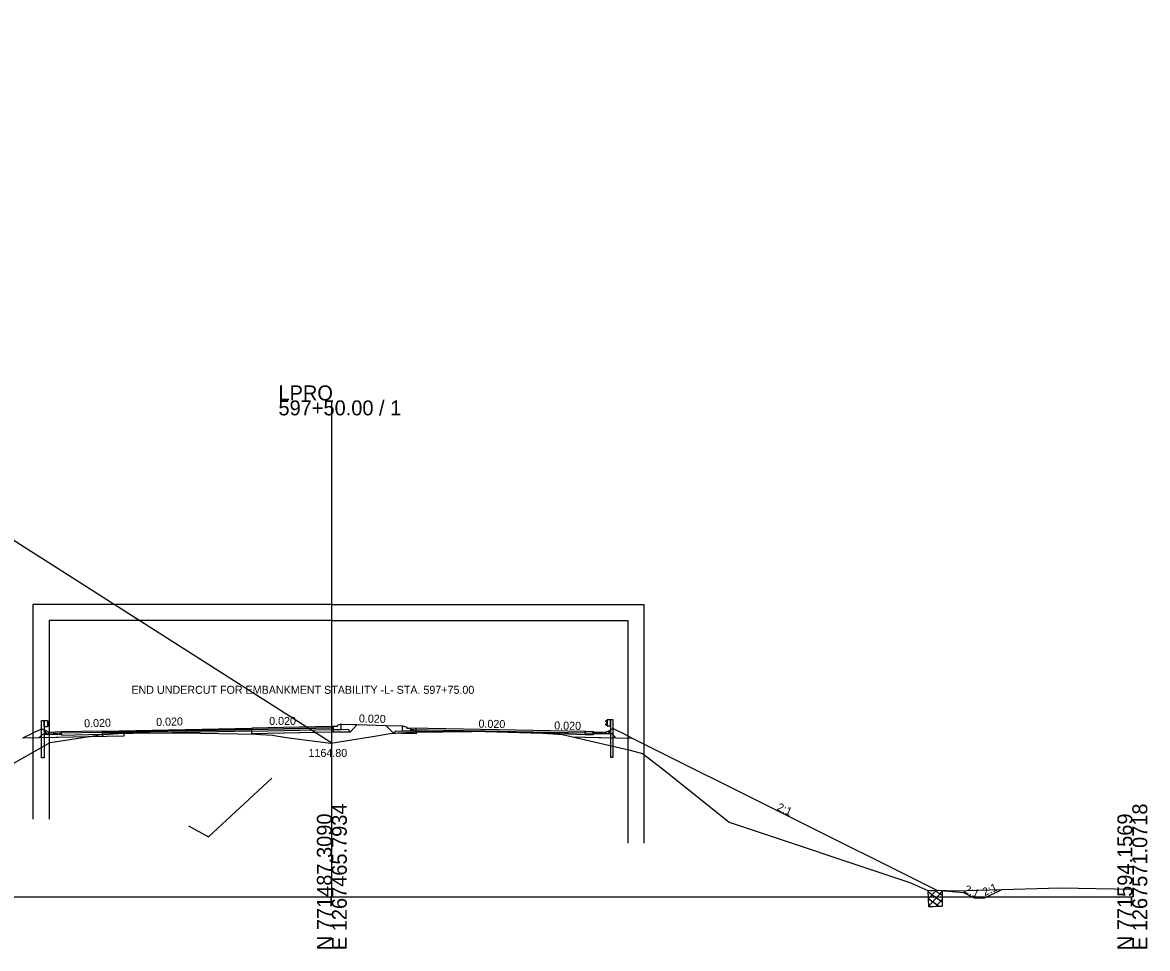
# Model space of a CAD drawing. Extents: x -3833 to 1267678, y -522 to 773248.
# Drawn here: x 92 to 302.8, y 8490.3 to 8663.9 of the extents above; entities that cross this region are included whole.
import ezdxf

# ---------------------------------------------------------------- set-up
doc = ezdxf.new("R2010")
doc.units = 0
for name, color, linetype in [('Exist Cross Section Cell', 7, 'Continuous'), ('Exist XS Center Line Elevation Label', 7, 'Continuous'), ('Exist XS Ground Line', 7, 'Continuous'), ('Prop CMT DNC', 7, 'Continuous'), ('Prop CMT Guardrail Graphics', 7, 'Continuous'), ('Prop CMT Pvmt Course 1', 7, 'Continuous'), ('Prop CMT Pvmt Course 2', 7, 'Continuous'), ('Prop CMT Pvmt Course 4', 7, 'Continuous'), ('Prop CMT Shld Paved Course 1', 7, 'Continuous'), ('Prop CMT Shld Paved Course 2', 7, 'Continuous'), ('Prop CMT Shld Paved Course 4', 7, 'Continuous'), ('Prop CMT Slope Grass', 7, 'Continuous'), ('Prop CMT Subgrade Earthwork', 7, 'Continuous'), ('Prop Conc Curb and Gutter', 7, 'Continuous'), ('Prop Conc Island Cover', 7, 'Continuous'), ('Prop Corridor Mesh Bottom', 7, 'Continuous'), ('Prop XS Ditch Slope Text', 7, 'Continuous'), ('Prop XS Finish Grade', 7, 'Continuous'), ('Prop XS Label Text', 7, 'Continuous'), ('Prop XS SE Text', 7, 'Continuous'), ('Prop XS Undercut Exc', 7, 'Continuous'), ('Scratch_Level_1', 7, 'Continuous'), ('Scratch_Level_3', 7, 'Continuous'), ('Scratch_Level_5', 7, 'Continuous'), ('Typical Curb CELL', 7, 'Continuous')]:
    doc.layers.add(name, color=color, linetype=linetype)

msp = doc.modelspace()

# ---------------------------------------------------------------- linework, layer by layer
at = {"layer": 'Exist Cross Section Cell'}
for p, q in [((150, 8500), (150, 8593.03)), ((0, 8500), (150, 8500)), ((150, 8500), (300, 8500))]:
    msp.add_line(p, q, dxfattribs=at)
at = {"layer": 'Exist XS Ground Line'}
for p, q in [((97.19, 8528.92), (105.76, 8530.24)), ((105.76, 8530.24), (106.67, 8530.39)), ((106.67, 8530.39), (107.2, 8530.42)), ((107.2, 8530.42), (110.96, 8530.64)), ((110.96, 8530.64), (112.73, 8530.65)), ((112.73, 8530.65), (122.54, 8530.7)), ((122.54, 8530.7), (125.34, 8530.65)), ((125.34, 8530.65), (135.95, 8530.46)), ((135.95, 8530.46), (136.62, 8530.42)), ((136.62, 8530.42), (138.94, 8530.31)), ((138.94, 8530.31), (139.56, 8530.17)), ((139.56, 8530.17), (141.91, 8529.8)), ((141.91, 8529.8), (148.29, 8528.98)), ((150.97, 8528.97), (157.63, 8530.03)), ((157.63, 8530.03), (160.94, 8530.63)), ((160.94, 8530.63), (162.02, 8530.68)), ((162.02, 8530.68), (162.38, 8530.7)), ((162.38, 8530.7), (165.35, 8530.83)), ((165.35, 8530.83), (176.22, 8531)), ((176.22, 8531), (176.62, 8531.01)), ((176.62, 8531.01), (178.72, 8530.95)), ((178.72, 8530.95), (189.53, 8530.67)), ((189.53, 8530.67), (193.23, 8530.4)), ((193.23, 8530.4), (200.22, 8528.78)), ((90.31, 8525), (97.19, 8528.92)), ((148.29, 8528.98), (149.81, 8528.76)), ((149.81, 8528.76), (150.97, 8528.97)), ((200.22, 8528.78), (205.63, 8527.53)), ((205.63, 8527.53), (208.23, 8526.86)), ((208.23, 8526.86), (212.2, 8523.77)), ((212.2, 8523.77), (224.47, 8513.99)), ((224.47, 8513.99), (258.31, 8502.67)), ((258.31, 8502.67), (261.7, 8501.2)), ((261.7, 8501.2), (262.71, 8501.17)), ((262.71, 8501.17), (263.74, 8501.24)), ((263.74, 8501.24), (266.72, 8501.14)), ((266.72, 8501.14), (286.47, 8501.67)), ((286.47, 8501.67), (300, 8501.43))]:
    msp.add_line(p, q, dxfattribs=at)
at = {"layer": 'Prop CMT Guardrail Graphics'}
for p, q in [((95.59, 8530.54), (95.59, 8533.04)), ((95.59, 8533.04), (96.07, 8533.04)), ((96.07, 8533.04), (96.07, 8530.53)), ((96.07, 8531.86), (96.07, 8533.04)), ((96.07, 8533.04), (96.74, 8533.04)), ((96.74, 8531.86), (96.07, 8531.86)), ((96.74, 8533.04), (96.74, 8531.86)), ((96.74, 8532.96), (96.74, 8531.93)), ((96.84, 8532.94), (96.74, 8532.96)), ((96.74, 8531.93), (96.84, 8531.96)), ((96.75, 8532.49), (96.98, 8532.69)), ((96.75, 8532.4), (96.75, 8532.49)), ((96.98, 8532.2), (96.75, 8532.4)), ((96.98, 8532.84), (96.84, 8532.94)), ((96.84, 8531.96), (96.98, 8532.06)), ((96.98, 8532.69), (96.98, 8532.84)), ((96.98, 8532.06), (96.98, 8532.2)), ((201.32, 8532.99), (201.46, 8533.09)), ((201.32, 8532.85), (201.32, 8532.99)), ((201.54, 8532.65), (201.32, 8532.85)), ((201.32, 8532.36), (201.54, 8532.56)), ((201.32, 8532.21), (201.32, 8532.36)), ((201.46, 8532.11), (201.32, 8532.21)), ((201.46, 8533.09), (201.56, 8533.11)), ((201.56, 8532.09), (201.46, 8532.11)), ((201.54, 8532.56), (201.54, 8532.65)), ((201.56, 8533.19), (201.56, 8532.01)), ((202.23, 8533.19), (201.56, 8533.19)), ((201.56, 8533.11), (201.56, 8532.09)), ((201.56, 8532.01), (202.23, 8532.01)), ((202.71, 8533.19), (202.23, 8533.19)), ((202.23, 8532.01), (202.23, 8533.19)), ((202.23, 8533.19), (202.23, 8530.68)), ((202.71, 8530.69), (202.71, 8533.19)), ((95.59, 8526.03), (95.59, 8530.54)), ((96.07, 8530.53), (96.07, 8526.03)), ((202.23, 8530.68), (202.23, 8526.18)), ((202.71, 8526.18), (202.71, 8530.69)), ((96.07, 8526.03), (95.59, 8526.03)), ((202.23, 8526.18), (202.71, 8526.18))]:
    msp.add_line(p, q, dxfattribs=at)
at = {"layer": 'Prop CMT Pvmt Course 1'}
for p, q in [((107, 8531.05), (135, 8531.61)), ((135, 8531.36), (107, 8530.8)), ((135, 8531.61), (135, 8531.61)), ((135, 8531.61), (135, 8531.61)), ((135, 8531.61), (135, 8531.36)), ((135, 8531.36), (135, 8531.36)), ((197.48, 8530.96), (164.78, 8531.61)), ((164.78, 8531.61), (164.78, 8531.61)), ((164.78, 8531.61), (164.78, 8531.61)), ((164.78, 8531.61), (164.78, 8531.36)), ((164.78, 8531.36), (197.48, 8530.71)), ((164.78, 8531.36), (165, 8531.36)), ((107, 8530.8), (107, 8531.05)), ((107, 8531.05), (107, 8531.05)), ((197.48, 8530.71), (197.48, 8530.96)), ((197.48, 8530.96), (197.48, 8530.96))]:
    msp.add_line(p, q, dxfattribs=at)
at = {"layer": 'Prop CMT Pvmt Course 2'}
for p, q in [((150, 8531.66), (135, 8531.36)), ((135, 8531.36), (135, 8531.36)), ((135, 8531.36), (135, 8531.03)), ((150.24, 8531.65), (150, 8531.66)), ((150, 8531.66), (150, 8531.66)), ((150, 8531.66), (150, 8531.66)), ((150.25, 8531.32), (150.24, 8531.65)), ((150.24, 8531.65), (150.24, 8531.65)), ((135, 8531.02), (150, 8531.33)), ((135, 8531.03), (135, 8531.02)), ((150, 8531.33), (150, 8531.33)), ((150, 8531.33), (150, 8531.33)), ((150, 8531.33), (150.25, 8531.32)), ((150.25, 8531.32), (150.25, 8531.32))]:
    msp.add_line(p, q, dxfattribs=at)
at = {"layer": 'Prop CMT Pvmt Course 4'}
for p, q in [((153.04, 8531.37), (150.25, 8531.32)), ((153.49, 8530.92), (153.04, 8531.37)), ((165.78, 8531.36), (165.78, 8531.59)), ((165.78, 8530.55), (165.78, 8531.36)), ((135, 8531.02), (150, 8531.33)), ((135, 8530.57), (135, 8531.03)), ((135, 8531.03), (135, 8531.03)), ((135, 8531.03), (135, 8531.02)), ((150, 8530.87), (135, 8530.57)), ((150, 8531.33), (150, 8531.33)), ((150, 8531.33), (150, 8531.33)), ((150, 8531.33), (150.25, 8531.32)), ((150.24, 8530.86), (150, 8530.87)), ((150, 8530.87), (150, 8530.87)), ((150, 8530.87), (150, 8530.87)), ((150.24, 8531.32), (150.24, 8530.86)), ((150.25, 8531.32), (150.24, 8531.32)), ((150.25, 8531.32), (150.24, 8530.86)), ((150.24, 8530.86), (153.49, 8530.92)), ((150.24, 8530.86), (150.24, 8530.86)), ((150.24, 8530.86), (150.24, 8530.86)), ((150.25, 8531.32), (150.25, 8531.32)), ((150.25, 8531.32), (150.25, 8531.32)), ((161.53, 8530.64), (161.98, 8531.08)), ((164.78, 8530.57), (161.53, 8530.64)), ((161.98, 8531.08), (164.78, 8531.03))]:
    msp.add_line(p, q, dxfattribs=at)
at = {"layer": 'Prop CMT Shld Paved Course 1'}
for p, q in [((150, 8531.91), (135, 8531.61)), ((135, 8531.36), (150, 8531.66)), ((135, 8531.61), (135, 8531.61)), ((135, 8531.61), (135, 8531.36)), ((150.24, 8531.9), (150, 8531.91)), ((150, 8531.91), (150, 8531.91)), ((150, 8531.91), (150, 8531.91)), ((150, 8531.66), (150, 8531.66)), ((150, 8531.66), (150, 8531.66)), ((150, 8531.66), (150.24, 8531.65)), ((150.24, 8531.65), (150.24, 8531.9)), ((150.24, 8531.9), (150.24, 8531.9)), ((164.78, 8531.36), (164.78, 8531.61)), ((96.99, 8530.52), (96.99, 8530.52)), ((96.99, 8530.52), (96.99, 8530.52)), ((97.01, 8530.81), (97.01, 8530.81)), ((97.01, 8530.81), (97.01, 8530.81)), ((97.01, 8530.81), (97.01, 8530.81)), ((97.01, 8530.81), (97.01, 8530.81)), ((97.01, 8530.81), (97.01, 8530.81)), ((97.19, 8530.51), (97.19, 8530.51)), ((97.19, 8530.51), (97.19, 8530.51)), ((97.19, 8530.51), (97.19, 8530.51)), ((97.19, 8530.51), (97.19, 8530.51)), ((97.19, 8530.51), (97.19, 8530.51)), ((97.19, 8530.51), (97.19, 8530.51)), ((107, 8531.05), (99.33, 8530.89)), ((107, 8530.8), (107, 8531.05)), ((107, 8531.05), (107, 8531.05)), ((107, 8531.05), (107, 8531.05)), ((107, 8530.8), (107, 8530.8)), ((197.48, 8530.96), (197.48, 8530.71)), ((198.99, 8530.93), (197.48, 8530.96)), ((197.48, 8530.71), (198.99, 8530.68))]:
    msp.add_line(p, q, dxfattribs=at)
at = {"layer": 'Prop CMT Shld Paved Course 2'}
for p, q in [((125.34, 8531.16), (135, 8531.36)), ((135, 8531.36), (135, 8531.36)), ((135, 8531.36), (135, 8531.36)), ((135, 8531.36), (135, 8531.02)), ((164.78, 8531.03), (164.78, 8531.36)), ((164.78, 8531.36), (164.78, 8531.36)), ((164.78, 8531.36), (165.35, 8531.35)), ((165.35, 8531.35), (165.35, 8531.35)), ((165.35, 8531.35), (165.35, 8531.35)), ((165.35, 8531.35), (176.22, 8531.13)), ((96.65, 8530.18), (96.65, 8530.18)), ((96.76, 8530.56), (96.76, 8530.56)), ((96.85, 8530.17), (96.85, 8530.17)), ((96.85, 8530.17), (96.85, 8530.17)), ((96.85, 8530.17), (96.85, 8530.17)), ((96.85, 8530.17), (96.85, 8530.17)), ((96.99, 8530.52), (96.99, 8530.52)), ((97.19, 8530.51), (97.19, 8530.51)), ((97.19, 8530.51), (97.19, 8530.51)), ((107, 8530.8), (99.33, 8530.64)), ((107, 8530.8), (112.73, 8530.91)), ((107, 8530.46), (107, 8530.8)), ((107, 8530.8), (107, 8530.8)), ((107, 8530.8), (107, 8530.8)), ((107, 8530.46), (107, 8530.8)), ((107, 8530.8), (107, 8530.8)), ((110.96, 8530.64), (107, 8530.46)), ((107, 8530.46), (107, 8530.46)), ((112.73, 8530.65), (110.96, 8530.64)), ((112.73, 8530.91), (122.54, 8531.11)), ((112.73, 8530.91), (112.73, 8530.91)), ((117.65, 8530.68), (112.73, 8530.65)), ((112.73, 8530.65), (112.73, 8530.65)), ((122.54, 8530.77), (117.65, 8530.68)), ((117.65, 8530.68), (117.65, 8530.68)), ((122.54, 8531.11), (125.34, 8531.16)), ((122.54, 8531.11), (122.54, 8531.11)), ((125.34, 8530.83), (122.54, 8530.77)), ((122.54, 8530.77), (122.54, 8530.77)), ((125.34, 8531.16), (125.34, 8531.16)), ((135, 8531.02), (125.34, 8530.83)), ((125.34, 8530.83), (125.34, 8530.83)), ((135, 8531.02), (135, 8531.02)), ((165.35, 8531.02), (164.78, 8531.03)), ((170.54, 8530.91), (165.35, 8531.02)), ((165.35, 8531.02), (165.35, 8531.02)), ((165.35, 8531.02), (165.35, 8531.02)), ((176.22, 8531), (170.54, 8530.91)), ((170.54, 8530.91), (170.54, 8530.91)), ((176.22, 8531.13), (176.22, 8531.13)), ((176.22, 8531.13), (176.62, 8531.12)), ((176.62, 8531.01), (176.22, 8531)), ((176.22, 8531), (176.22, 8531)), ((176.62, 8531.12), (178.72, 8531.08)), ((178.72, 8530.95), (176.62, 8531.01)), ((178.72, 8531.08), (178.72, 8531.08)), ((178.72, 8531.08), (189.53, 8530.87)), ((189.53, 8530.67), (178.72, 8530.95)), ((178.72, 8530.95), (178.72, 8530.95)), ((189.53, 8530.87), (189.53, 8530.87)), ((189.53, 8530.87), (189.8, 8530.86)), ((189.8, 8530.65), (189.53, 8530.67)), ((189.53, 8530.67), (189.53, 8530.67)), ((189.8, 8530.86), (197.48, 8530.71)), ((197.48, 8530.38), (189.8, 8530.65)), ((197.48, 8530.71), (197.48, 8530.71)), ((197.48, 8530.71), (197.48, 8530.38)), ((197.48, 8530.71), (197.48, 8530.38))]:
    msp.add_line(p, q, dxfattribs=at)
at = {"layer": 'Prop CMT Shld Paved Course 4'}
for p, q in [((95.1, 8529.76), (95.82, 8530.48)), ((95.82, 8530.48), (96.32, 8530.48)), ((107, 8530.01), (95.94, 8529.78)), ((99.34, 8530.48), (99.34, 8530.31)), ((99.34, 8530.31), (107, 8530.46)), ((107, 8530.46), (107, 8530.01)), ((197.48, 8530.38), (189.8, 8530.65)), ((189.8, 8530.65), (193.23, 8530.4)), ((193.23, 8530.4), (195.12, 8529.97)), ((195.12, 8529.97), (202.39, 8529.82)), ((198.99, 8530.35), (197.48, 8530.38)), ((198.99, 8530.51), (198.99, 8530.35)), ((202.52, 8530.51), (202.01, 8530.51)), ((203.23, 8529.8), (202.52, 8530.51))]:
    msp.add_line(p, q, dxfattribs=at)
at = {"layer": 'Prop CMT Slope Grass'}
for p, q in [((95.63, 8531.5), (93.71, 8530.55)), ((95.63, 8531.5), (96.32, 8531.15)), ((151.87, 8532.33), (154.77, 8532.26)), ((160.1, 8532.12), (163.27, 8532.04)), ((202.71, 8531.54), (202.01, 8531.19)), ((202.71, 8531.54), (204.62, 8530.58)), ((93.71, 8530.55), (92.03, 8529.71)), ((204.62, 8530.58), (206.3, 8529.74))]:
    msp.add_line(p, q, dxfattribs=at)
at = {"layer": 'Prop CMT Subgrade Earthwork'}
for p, q in [((153.49, 8530.92), (154.77, 8532.26)), ((161.53, 8530.64), (160.1, 8532.12)), ((111, 8530.09), (92.03, 8529.71)), ((111, 8530.64), (111, 8530.09)), ((150.24, 8530.86), (135, 8530.57)), ((135, 8530.57), (135, 8530.48)), ((153.49, 8530.92), (150.24, 8530.86)), ((165.78, 8530.55), (161.53, 8530.64)), ((165.78, 8530.84), (165.78, 8530.55)), ((195.12, 8529.97), (197.47, 8529.92)), ((197.47, 8529.92), (206.3, 8529.74))]:
    msp.add_line(p, q, dxfattribs=at)
at = {"layer": 'Prop Conc Curb and Gutter'}
for p, q in [((150.24, 8531.9), (150.24, 8531.9)), ((150.24, 8531.9), (150.24, 8531.32)), ((150.25, 8531.9), (150.24, 8531.9)), ((150.99, 8531.92), (150.25, 8531.9)), ((150.25, 8531.32), (151.75, 8531.35)), ((151, 8531.92), (150.99, 8531.92)), ((151.75, 8532.33), (151, 8532.08)), ((151, 8532.08), (151, 8532.08)), ((151, 8532.08), (151, 8531.92)), ((151.76, 8532.33), (151.75, 8532.33)), ((151.75, 8531.35), (151.76, 8531.35)), ((151.76, 8531.35), (151.76, 8532.33)), ((151.76, 8532.33), (151.76, 8532.33)), ((163.27, 8532.03), (163.27, 8532.04)), ((163.27, 8532.04), (163.28, 8532.04)), ((163.27, 8531.06), (163.27, 8532.03)), ((163.28, 8532.04), (164.03, 8531.79)), ((164.03, 8531.79), (164.03, 8531.79)), ((164.03, 8531.79), (164.03, 8531.63)), ((164.03, 8531.63), (164.04, 8531.63)), ((164.04, 8531.63), (164.78, 8531.61)), ((164.78, 8531.61), (164.78, 8531.61)), ((164.78, 8531.61), (164.78, 8531.03)), ((150.24, 8531.32), (150.25, 8531.32)), ((163.29, 8531.06), (163.27, 8531.06)), ((164.78, 8531.03), (163.29, 8531.06))]:
    msp.add_line(p, q, dxfattribs=at)
at = {"layer": 'Prop Conc Island Cover'}
for p, q in [((151.76, 8532.08), (151.76, 8532.33)), ((151.76, 8532.33), (151.87, 8532.33)), ((163.27, 8532.04), (163.27, 8531.79))]:
    msp.add_line(p, q, dxfattribs=at)
at = {"layer": 'Prop Corridor Mesh Bottom'}
for p, q in [((135, 8531.61), (135, 8531.36)), ((111, 8531.13), (111, 8530.88))]:
    msp.add_line(p, q, dxfattribs=at)
at = {"layer": 'Prop XS Finish Grade'}
for p, q in [((151.76, 8532.33), (151.87, 8532.33)), ((153.91, 8532.28), (154.19, 8532.27)), ((154.77, 8532.26), (160.1, 8532.12)), ((206.3, 8529.74), (263.36, 8501.21))]:
    msp.add_line(p, q, dxfattribs=at)
msp.add_lwpolyline([(263.36, 8501.21), (268.36, 8500.8), (270.36, 8499.8), (272.36, 8499.8), (275.54, 8501.39)], dxfattribs=at)
at = {"layer": 'Prop XS Undercut Exc'}
for p, q in [((261.7, 8501.2), (261.78, 8498.19)), ((261.84, 8501.19), (261.7, 8501.05)), ((261.71, 8500.91), (264.36, 8499.08)), ((263.21, 8501.2), (261.74, 8499.62)), ((264.36, 8500.97), (261.79, 8498.19)), ((263.06, 8501.19), (264.36, 8500.3)), ((264.36, 8501.22), (264.36, 8498.22)), ((261.74, 8499.67), (263.82, 8498.24)), ((261.77, 8498.44), (262.14, 8498.18)), ((261.78, 8498.19), (262.77, 8498.16)), ((262.77, 8498.16), (263.8, 8498.24)), ((264.36, 8499.5), (263.15, 8498.19)), ((263.8, 8498.24), (264.36, 8498.22))]:
    msp.add_line(p, q, dxfattribs=at)
at = {"layer": 'Scratch_Level_1'}
msp.add_line((150, 8528.8), (-62.25, 8663.86), dxfattribs=at)
at = {"layer": 'Scratch_Level_3'}
msp.add_lwpolyline([(111, 8530.64), (111, 8530.09)], dxfattribs=at)
at = {"layer": 'Scratch_Level_5'}
for p, q in [((126.9, 8511.21), (138.76, 8522.24)), ((123.11, 8513.32), (126.9, 8511.21))]:
    msp.add_line(p, q, dxfattribs=at)
for points in [[(150, 8554.8), (94, 8554.8), (94, 8514.54)], [(150, 8554.8), (208.45, 8554.8), (208.45, 8510.08)], [(150, 8551.8), (97, 8551.8), (97, 8514.54)], [(150, 8551.8), (205.45, 8551.8), (205.45, 8510.08)]]:
    msp.add_lwpolyline(points, dxfattribs=at)
at = {"layer": 'Typical Curb CELL'}
for p, q in [((96.32, 8530.48), (96.32, 8531.15)), ((97.01, 8530.81), (96.32, 8531.15)), ((96.32, 8530.48), (99.34, 8530.48)), ((96.36, 8530.78), (96.51, 8530.82)), ((96.5, 8530.73), (96.36, 8530.78)), ((96.51, 8530.82), (96.5, 8530.73)), ((97.03, 8530.69), (96.93, 8530.62)), ((96.93, 8530.62), (97.09, 8530.58)), ((99.33, 8530.89), (97.01, 8530.81)), ((97.09, 8530.58), (97.03, 8530.69)), ((97.77, 8530.75), (97.74, 8530.64)), ((97.74, 8530.64), (97.86, 8530.63)), ((97.86, 8530.63), (97.77, 8530.75)), ((98.28, 8530.69), (98.18, 8530.62)), ((98.18, 8530.62), (98.34, 8530.58)), ((98.34, 8530.58), (98.28, 8530.69)), ((99.02, 8530.75), (98.99, 8530.64)), ((98.99, 8530.64), (99.11, 8530.63)), ((99.11, 8530.63), (99.02, 8530.75)), ((99.34, 8530.89), (99.34, 8530.89)), ((99.34, 8530.48), (99.34, 8530.88)), ((198.99, 8530.93), (198.99, 8530.93)), ((198.99, 8530.51), (198.99, 8530.92)), ((202.01, 8530.51), (198.99, 8530.51)), ((199, 8530.93), (201.33, 8530.84)), ((199.23, 8530.66), (199.32, 8530.78)), ((199.35, 8530.67), (199.23, 8530.66)), ((199.32, 8530.78), (199.35, 8530.67)), ((200, 8530.61), (200.06, 8530.73)), ((200.16, 8530.65), (200, 8530.61)), ((200.06, 8530.73), (200.16, 8530.65)), ((200.48, 8530.66), (200.57, 8530.78)), ((200.6, 8530.67), (200.48, 8530.66)), ((200.57, 8530.78), (200.6, 8530.67)), ((201.25, 8530.61), (201.31, 8530.73)), ((201.41, 8530.65), (201.25, 8530.61)), ((201.31, 8530.73), (201.41, 8530.65)), ((201.33, 8530.84), (202.01, 8531.19)), ((201.82, 8530.85), (201.84, 8530.76)), ((201.98, 8530.81), (201.82, 8530.85)), ((201.84, 8530.76), (201.98, 8530.81)), ((202.01, 8530.51), (202.01, 8531.19))]:
    msp.add_line(p, q, dxfattribs=at)
for centre in [(96.39, 8530.86), (96.49, 8530.59), (96.61, 8530.64), (96.86, 8530.67), (96.88, 8530.62), (97.06, 8530.53), (97.08, 8530.63), (97.28, 8530.59), (97.33, 8530.71), (97.45, 8530.68), (97.48, 8530.55), (97.54, 8530.59), (97.73, 8530.59), (97.85, 8530.64), (97.95, 8530.63), (98.04, 8530.58), (98.1, 8530.73), (98.11, 8530.67), (98.13, 8530.62), (98.33, 8530.63), (98.53, 8530.59), (98.57, 8530.71), (98.62, 8530.68), (98.7, 8530.68), (98.73, 8530.55), (98.79, 8530.59), (98.85, 8530.77), (99.22, 8530.84), (99.25, 8530.72), (199.08, 8530.75), (199.12, 8530.87), (199.49, 8530.8), (199.55, 8530.62), (199.6, 8530.59), (199.64, 8530.71), (199.71, 8530.71), (199.76, 8530.74), (199.81, 8530.63), (200, 8530.67), (200.21, 8530.65), (200.23, 8530.7), (200.24, 8530.76), (200.29, 8530.62), (200.39, 8530.66), (200.48, 8530.67), (200.6, 8530.62), (200.8, 8530.62), (200.85, 8530.59), (200.89, 8530.71), (201.01, 8530.74), (201.06, 8530.63), (201.25, 8530.67), (201.28, 8530.56), (201.46, 8530.65), (201.48, 8530.7), (201.73, 8530.67), (201.85, 8530.62), (201.95, 8530.89)]:
    msp.add_circle(centre, 0.00802, dxfattribs=at)
for centre, start, end in [((99.33, 8530.88), 0, 92.048), ((199, 8530.92), 87.952, 180)]:
    msp.add_arc(centre, 0.0104, start, end, dxfattribs=at)

# ---------------------------------------------------------------- texts
at = {"layer": 'Exist Cross Section Cell'}
for s, p in [('LPRO', (140, 8593.03)), ('597+50.00 / 1', (140, 8590.23))]:
    msp.add_text(s, height=2.8, dxfattribs=at).set_placement(p)
for s, p in [('E 1267465.7934', (152.8, 8490)), ('E 1267571.0718', (302.8, 8490)), ('N 771487.3090', (150, 8490)), ('N 771594.1569', (300, 8490))]:
    msp.add_text(s, height=2.8, rotation=90, dxfattribs=at).set_placement(p)
at = {"layer": 'Exist XS Center Line Elevation Label'}
for s, p in [('END UNDERCUT FOR EMBANKMENT STABILITY -L- STA. 597+75.00', (112.44, 8538.04)), ('1164.80', (145.63, 8526.21))]:
    msp.add_text(s, height=1.5, dxfattribs=at).set_placement(p)
at = {"layer": 'Prop CMT DNC'}
for p in [(135, 8531.61), (135, 8531.61), (150, 8531.91), (150.99, 8531.92), (164.03, 8531.63), (165, 8531.61), (165, 8531.61), (101, 8530.93), (111, 8531.13), (111, 8531.13), (191.03, 8531.09), (199, 8530.93), (264.29, 8501.22)]:
    msp.add_text('X', height=0.00025, dxfattribs=at).set_placement(p)
at = {"layer": 'Prop XS Ditch Slope Text'}
msp.add_text('2:1', height=1.5, rotation=335.81, dxfattribs=at).set_placement((233.27, 8516.29))
at = {"layer": 'Prop XS Label Text'}
for rotation, p in [(335.0633, (268.33, 8500.92)), (24.9367, (272.33, 8500.1))]:
    msp.add_text('2:1', height=1.5, rotation=rotation, dxfattribs=at).set_placement(p)
at = {"layer": 'Prop XS SE Text'}
for rotation, p in [(1.397, (117.09, 8532.01)), (0.2693, (138.26, 8532.2)), (358.8542, (155.06, 8532.68)), (1.397, (103.6, 8531.76)), (358.8542, (177.47, 8531.71)), (358.8542, (191.66, 8531.37))]:
    msp.add_text('0.020', height=1.5, rotation=rotation, dxfattribs=at).set_placement(p)

doc.saveas('drawing.dxf')
